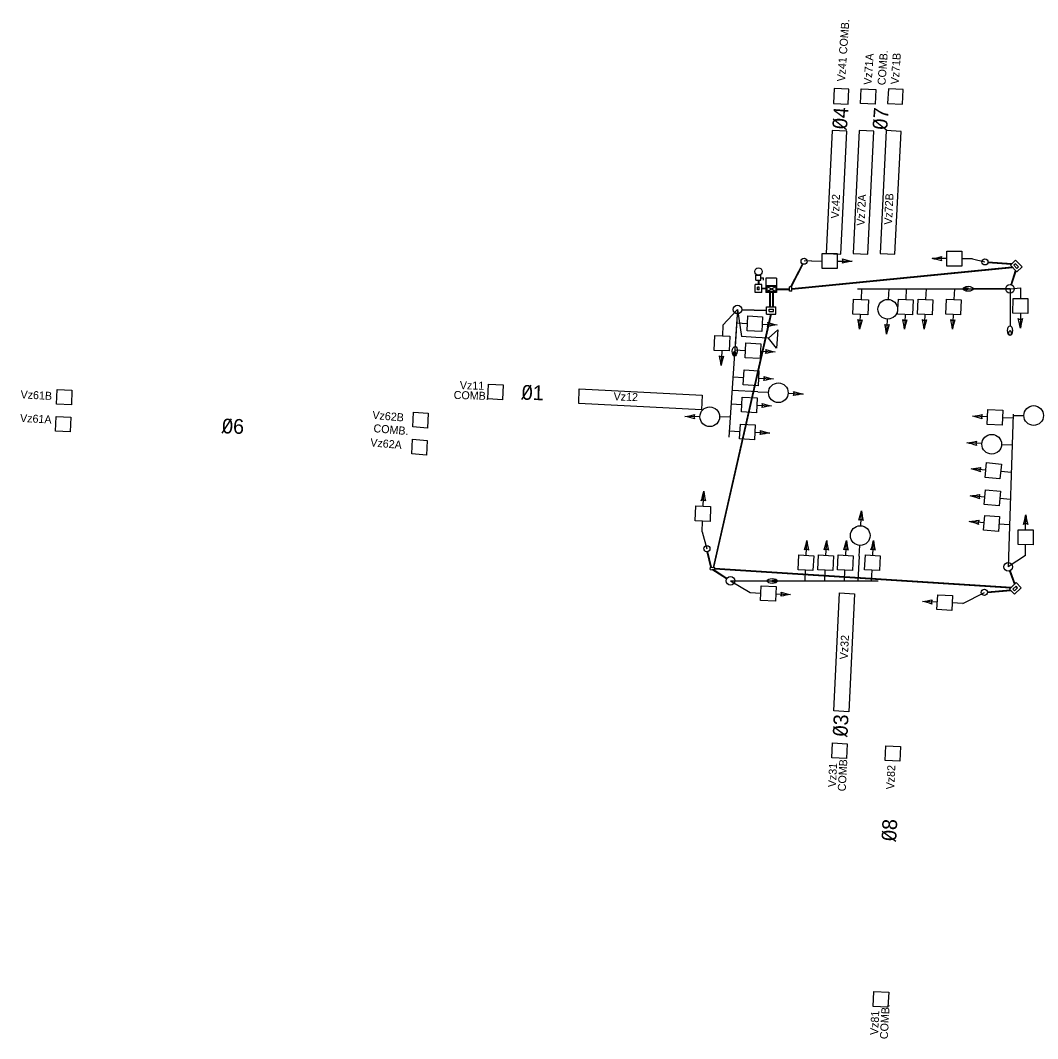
# Model space of a CAD drawing. Extents: x 647787 to 668496, y 640478 to 654412.
# Drawn here: x 647787.3 to 648200.7, y 648285.9 to 648699.5 of the extents above; entities that cross this region are included whole.
import ezdxf

# ---------------------------------------------------------------- set-up
doc = ezdxf.new("R2010")
doc.units = 0
for name, color, linetype in [('Default', 7, 'Continuous'), ('TEMP_SIGNAL_HEAD_STAGE 1A', 7, 'Continuous'), ('TEMP_SIGNAL_POLES_STAGE 1A', 7, 'Continuous'), ('TEMP_SIGNAL_POLES_STAGE 1B', 7, 'Continuous'), ('TEXT_TEMP_SIGNAL_POLES_STAGE 5', 7, 'Continuous')]:
    doc.layers.add(name, color=color, linetype=linetype)

msp = doc.modelspace()

# ---------------------------------------------------------------- linework, layer by layer
at = {"layer": 'Default'}
for p, q in [((648117.56, 648659.45), (648123, 648655.19)), ((648133.9, 648659.21), (648139.34, 648654.95)), ((647990.99, 648545.5), (647994.86, 648551.28)), ((647869.23, 648531.84), (647873.1, 648537.62)), ((648117.67, 648412.67), (648123.23, 648408.56)), ((648137.49, 648370.17), (648143.05, 648366.07))]:
    msp.add_line(p, q, dxfattribs=at)
at = {"layer": 'TEMP_SIGNAL_HEAD_STAGE 1A'}
for p, q in [((648105.08, 648600.6), (648100.19, 648591.24)), ((648105.3, 648600.49), (648100.47, 648591.23)), ((648100.79, 648590.53), (648190.24, 648599.38)), ((648100.79, 648590.28), (648190.47, 648599.15)), ((648189.91, 648600.32), (648180.42, 648601.03)), ((648190.14, 648600.55), (648180.47, 648601.28)), ((648191.68, 648602.07), (648189.61, 648600.02)), ((648192.25, 648597.36), (648189.61, 648600.02)), ((648191.67, 648600.66), (648191.02, 648600.01)), ((648192.25, 648598.77), (648191.02, 648600.01)), ((648192.9, 648599.42), (648191.67, 648600.66)), ((648194.32, 648599.41), (648191.68, 648602.07)), ((648192.9, 648599.42), (648192.25, 648598.77)), ((648194.32, 648599.41), (648192.25, 648597.36)), ((648086.19, 648595.95), (648088.19, 648595.95)), ((648086.19, 648593.95), (648086.19, 648595.95)), ((648088.19, 648593.95), (648088.19, 648595.95)), ((648088.19, 648594.95), (648089.19, 648594.95)), ((648089.19, 648593.95), (648089.19, 648594.95)), ((648189.84, 648592.17), (648191.68, 648597.93)), ((648190.08, 648592.1), (648191.88, 648597.73)), ((648085.82, 648588.99), (648085.82, 648592.18)), ((648088.55, 648592.18), (648085.82, 648592.18)), ((648086.19, 648593.95), (648088.19, 648593.95)), ((648086.82, 648589.99), (648086.82, 648591.18)), ((648087.55, 648591.18), (648086.82, 648591.18)), ((648087.06, 648593.95), (648087.06, 648592.18)), ((648087.31, 648593.95), (648087.31, 648592.18)), ((648087.55, 648589.99), (648087.55, 648591.18)), ((648088.55, 648588.99), (648088.55, 648592.18)), ((648099.87, 648589.49), (648099.88, 648591.24)), ((648100.79, 648591.23), (648099.88, 648591.24)), ((648100.78, 648589.48), (648100.79, 648591.23)), ((648088.55, 648588.99), (648085.82, 648588.99)), ((648087.55, 648589.99), (648086.82, 648589.99)), ((648090.26, 648590.59), (648088.55, 648590.66)), ((648090.26, 648590.34), (648088.55, 648590.41)), ((648091.66, 648588.99), (648091.66, 648583.14)), ((648091.91, 648588.99), (648091.91, 648583.14)), ((648092.91, 648588.99), (648092.91, 648583.14)), ((648093.16, 648588.99), (648093.16, 648583.14)), ((648094.59, 648590.49), (648099.87, 648590.49)), ((648094.59, 648590.24), (648099.87, 648590.24)), ((648100.78, 648589.48), (648099.87, 648589.49)), ((648090.54, 648583.14), (648094.29, 648583.14)), ((648090.54, 648580.22), (648090.54, 648583.14)), ((648094.29, 648580.22), (648094.29, 648583.14)), ((648092.06, 648580.22), (648068.75, 648477.3)), ((648092.31, 648580.22), (648069, 648477.28)), ((648080.47, 648581.86), (648090.54, 648581.58)), ((648080.48, 648582.11), (648090.54, 648581.83)), ((648090.54, 648580.22), (648094.29, 648580.22)), ((648091.54, 648581.22), (648091.54, 648582.14)), ((648091.54, 648582.14), (648093.29, 648582.14)), ((648091.54, 648581.22), (648093.29, 648581.22)), ((648093.29, 648581.22), (648093.29, 648582.14)), ((648067.91, 648477.34), (648066.4, 648483.62)), ((648068.18, 648477.33), (648066.64, 648483.68)), ((648067.62, 648476.44), (648067.67, 648477.35)), ((648067.62, 648476.44), (648069.37, 648476.35)), ((648067.67, 648477.35), (648069.42, 648477.26)), ((648074.25, 648472.62), (648068.24, 648476.4)), ((648074.39, 648472.83), (648068.75, 648476.38)), ((648069.37, 648476.35), (648069.42, 648477.26)), ((648069.39, 648476.67), (648189.81, 648469.04)), ((648069.4, 648476.92), (648190.05, 648469.28)), ((648189.21, 648475.82), (648191.19, 648470.41)), ((648189.45, 648475.91), (648191.38, 648470.6)), ((648189.23, 648468.46), (648191.89, 648471.1)), ((648193.94, 648469.03), (648191.89, 648471.1)), ((648180.25, 648467.38), (648189.54, 648468.14)), ((648180.27, 648467.13), (648189.77, 648467.91)), ((648191.28, 648466.39), (648189.23, 648468.46)), ((648190.64, 648468.46), (648191.88, 648469.69)), ((648191.29, 648467.81), (648190.64, 648468.46)), ((648191.28, 648466.39), (648193.94, 648469.03)), ((648191.29, 648467.81), (648192.53, 648469.04)), ((648192.53, 648469.04), (648191.88, 648469.69))]:
    msp.add_line(p, q, dxfattribs=at)
msp.add_circle((648087.19, 648597.45), 1.5, dxfattribs=at)
at = {"layer": 'TEMP_SIGNAL_POLES_STAGE 1A'}
for p, q in [((648108.8, 648601.77), (648105.76, 648601.65)), ((648108.8, 648601.77), (648113.15, 648601.75)), ((648119.21, 648601.73), (648125.25, 648601.7)), ((648163.79, 648602.71), (648157.75, 648602.74)), ((648174.2, 648602.67), (648169.85, 648602.69)), ((648174.2, 648602.67), (648179.22, 648601.38)), ((648189.43, 648590.47), (648193.72, 648590.9)), ((648193.72, 648590.9), (648193.7, 648586.55)), ((648127.43, 648590.47), (648189.43, 648590.47)), ((648129.1, 648590.47), (648128.89, 648586.13)), ((648140.16, 648590.47), (648139.95, 648586.15)), ((648147.29, 648590.47), (648147.08, 648586.13)), ((648155.3, 648590.47), (648155.09, 648586.13)), ((648166.81, 648590.47), (648166.61, 648586.13)), ((648189.43, 648590.47), (648174.43, 648590.47)), ((648189.43, 648590.47), (648189.43, 648575.47)), ((648072.7, 648575.74), (648078.73, 648582.03)), ((648078.73, 648582.03), (648075.18, 648530.15)), ((648078.73, 648582.03), (648077.7, 648567.06)), ((648078.73, 648582.03), (648080.25, 648571.03)), ((648128.6, 648580.07), (648128.31, 648574.04)), ((648146.79, 648580.07), (648146.51, 648574.04)), ((648154.8, 648580.07), (648154.51, 648574.04)), ((648166.32, 648580.07), (648166.03, 648574.04)), ((648193.67, 648580.49), (648193.65, 648574.45)), ((648072.7, 648575.74), (648072.53, 648571.4)), ((648078.36, 648576.62), (648082.7, 648576.4)), ((648088.75, 648576.09), (648094.79, 648575.79)), ((648139.57, 648578.15), (648139.28, 648572.1)), ((648086.12, 648570.68), (648080.25, 648571.03)), ((648072.29, 648565.34), (648072.05, 648559.31)), ((648077.61, 648565.64), (648081.95, 648565.42)), ((648088, 648565.12), (648094.04, 648564.81)), ((648076.85, 648554.67), (648081.2, 648554.45)), ((648087.25, 648554.14), (648093.28, 648553.83)), ((648086.97, 648548.65), (648076.48, 648549.18)), ((648086.97, 648548.65), (648091.3, 648548.43)), ((648099.29, 648548.02), (648105.34, 648547.71)), ((648076.1, 648543.69), (648080.44, 648543.47)), ((648086.5, 648543.16), (648092.53, 648542.86)), ((648063.41, 648538.5), (648057.34, 648538.56)), ((648075.74, 648538.37), (648071.41, 648538.42)), ((648180.28, 648538.4), (648174.24, 648538.71)), ((648190.67, 648537.87), (648186.33, 648538.09)), ((648190.72, 648539.48), (648188.73, 648477.51)), ((648190.71, 648538.94), (648195.04, 648538.96)), ((648075.35, 648532.72), (648079.69, 648532.49)), ((648085.75, 648532.19), (648091.78, 648531.88)), ((648178.01, 648527.56), (648171.95, 648527.9)), ((648190.32, 648526.88), (648186, 648527.12)), ((648179.6, 648516.82), (648173.58, 648517.37)), ((648189.97, 648515.88), (648185.64, 648516.27)), ((648064.74, 648502.18), (648064.98, 648508.21)), ((648179.25, 648505.83), (648173.23, 648506.37)), ((648189.61, 648504.88), (648185.28, 648505.28)), ((648128.75, 648494.23), (648129.05, 648500.29)), ((648064.33, 648491.78), (648064.5, 648496.12)), ((648178.91, 648495.41), (648172.89, 648495.93)), ((648195.78, 648492.58), (648195.8, 648498.62)), ((648064.33, 648491.78), (648066.23, 648484.86)), ((648189.28, 648494.52), (648184.95, 648494.89)), ((648106.63, 648482.19), (648106.93, 648488.22)), ((648114.64, 648482.19), (648114.94, 648488.22)), ((648122.65, 648482.19), (648122.95, 648488.22)), ((648133.66, 648482.19), (648133.96, 648488.22)), ((648128.14, 648481.92), (648128.36, 648486.24)), ((648195.74, 648482.17), (648195.75, 648486.52)), ((648128.14, 648481.92), (648127.65, 648471.79)), ((648195.74, 648482.17), (648188.73, 648477.51)), ((648106.12, 648471.79), (648106.33, 648476.13)), ((648114.13, 648471.79), (648114.34, 648476.13)), ((648122.14, 648471.79), (648122.35, 648476.13)), ((648133.15, 648471.79), (648133.37, 648476.13)), ((648075.8, 648471.79), (648135.8, 648471.79)), ((648075.8, 648471.79), (648083.85, 648467.06)), ((648075.8, 648471.79), (648090.8, 648471.79)), ((648083.85, 648467.07), (648088.2, 648466.85)), ((648170.29, 648462.64), (648179.02, 648467.16)), ((648094.25, 648466.54), (648100.28, 648466.23)), ((648159.89, 648463.17), (648153.86, 648463.48)), ((648170.29, 648462.64), (648165.95, 648462.86))]:
    msp.add_line(p, q, dxfattribs=at)
for points in [[(648113.14, 648598.72), (648113.16, 648604.78), (648119.23, 648604.76), (648119.2, 648598.69)], [(648169.86, 648605.72), (648169.84, 648599.65), (648163.78, 648599.68), (648163.8, 648605.74)], [(648125.86, 648586.27), (648131.92, 648585.98), (648131.63, 648579.93), (648125.57, 648580.22)], [(648144.05, 648586.27), (648150.11, 648585.98), (648149.82, 648579.93), (648143.76, 648580.22)], [(648152.06, 648586.27), (648158.12, 648585.98), (648157.83, 648579.93), (648151.77, 648580.22)], [(648163.58, 648586.27), (648169.63, 648585.98), (648169.34, 648579.93), (648163.29, 648580.22)], [(648190.67, 648586.57), (648196.73, 648586.54), (648196.71, 648580.48), (648190.64, 648580.5)], [(648082.55, 648573.37), (648082.85, 648579.43), (648088.91, 648579.12), (648088.6, 648573.06)], [(648069.5, 648571.52), (648075.56, 648571.28), (648075.32, 648565.22), (648069.26, 648565.46)], [(648081.79, 648562.39), (648082.1, 648568.45), (648088.16, 648568.14), (648087.85, 648562.09)], [(648081.04, 648551.42), (648081.35, 648557.48), (648087.4, 648557.17), (648087.1, 648551.11)], [(648080.29, 648540.44), (648080.6, 648546.5), (648086.65, 648546.19), (648086.35, 648540.14)], [(648186.49, 648541.12), (648186.18, 648535.06), (648180.12, 648535.37), (648180.43, 648541.43)], [(648079.54, 648529.47), (648079.85, 648535.52), (648085.9, 648535.22), (648085.59, 648529.16)], [(648185.91, 648519.29), (648185.36, 648513.25), (648179.32, 648513.8), (648179.87, 648519.84)], [(648185.56, 648508.3), (648185.01, 648502.26), (648178.97, 648502.81), (648179.52, 648508.85)], [(648067.53, 648496), (648061.47, 648496.24), (648061.71, 648502.3), (648067.77, 648502.06)], [(648185.21, 648497.91), (648184.69, 648491.87), (648178.65, 648492.39), (648179.17, 648498.43)], [(648198.79, 648486.51), (648192.72, 648486.53), (648192.75, 648492.6), (648198.81, 648492.57)], [(648109.36, 648475.98), (648103.3, 648476.28), (648103.6, 648482.34), (648109.66, 648482.04)], [(648117.37, 648475.98), (648111.31, 648476.28), (648111.61, 648482.34), (648117.67, 648482.04)], [(648125.38, 648475.98), (648119.32, 648476.28), (648119.62, 648482.34), (648125.68, 648482.04)], [(648136.39, 648475.98), (648130.34, 648476.28), (648130.64, 648482.34), (648136.69, 648482.04)], [(648088.04, 648463.82), (648088.35, 648469.87), (648094.4, 648469.57), (648094.1, 648463.51)], [(648166.1, 648465.89), (648165.8, 648459.83), (648159.74, 648460.14), (648160.05, 648466.2)]]:
    msp.add_lwpolyline(points, close=True, dxfattribs=at)
msp.add_lwpolyline([(648091.23, 648570.37), (648095.04, 648573.75), (648094.6, 648566.38), (648091.23, 648570.37), (648086.12, 648570.68)], dxfattribs=at)
for centre, radius in [((648105.76, 648601.65), 1.25), ((648179.22, 648601.38), 1.25), ((648189.43, 648590.47), 1.75), ((648078.73, 648582.03), 1.75), ((648139.76, 648582.15), 4), ((648095.29, 648548.22), 4), ((648067.41, 648538.46), 4), ((648199.04, 648538.99), 4), ((648182, 648527.34), 4), ((648128.55, 648490.24), 4), ((648066.23, 648484.86), 1.25), ((648188.73, 648477.51), 1.75), ((648075.8, 648471.79), 1.75), ((648179.02, 648467.16), 1.25)]:
    msp.add_circle(centre, radius, dxfattribs=at)
for centre, radius, start, end in [((648153.45, 648631.89), 29.47, 278.3758, 286.1139), ((648163.01, 648602.71), 1.63, 147.9202, 211.6148), ((648119.99, 648601.72), 1.63, 327.9202, 31.6148), ((648129.78, 648630.82), 29.47, 253.421, 261.1592), ((648129.55, 648572.54), 29.47, 98.3758, 106.1139), ((648153.22, 648573.61), 29.47, 73.421, 81.1592), ((648193.67, 648579.72), 1.63, 237.9208, 301.6154), ((648164.49, 648570.16), 29.47, 8.3764, 16.1145), ((648222.77, 648569.92), 29.47, 163.4217, 171.1598), ((648089.53, 648576.05), 1.63, 325.2481, 28.9427), ((648097.72, 648546.46), 29.47, 95.7037, 103.4418), ((648100.67, 648604.66), 29.47, 250.749, 258.4871), ((648128.56, 648579.3), 1.63, 235.4157, 299.1103), ((648098.99, 648571.02), 29.47, 5.8713, 13.6095), ((648157.21, 648568.24), 29.47, 160.9166, 168.6547), ((648139.53, 648577.36), 1.63, 235.4131, 299.1077), ((648109.96, 648569.08), 29.47, 5.8797, 13.6179), ((648168.17, 648566.3), 29.47, 160.9241, 168.6622), ((648146.76, 648579.3), 1.63, 235.4157, 299.1103), ((648117.19, 648571.02), 29.47, 5.8713, 13.6095), ((648175.4, 648568.24), 29.47, 160.9166, 168.6547), ((648154.77, 648579.3), 1.63, 235.4157, 299.1103), ((648125.2, 648571.02), 29.47, 5.8713, 13.6095), ((648183.41, 648568.24), 29.47, 160.9166, 168.6547), ((648166.28, 648579.3), 1.63, 235.4157, 299.1103), ((648136.71, 648571.02), 29.47, 5.8713, 13.6095), ((648194.92, 648568.24), 29.47, 160.9166, 168.6547), ((648072.26, 648564.57), 1.63, 235.8929, 299.5875), ((648042.76, 648556.05), 29.47, 6.3485, 14.0866), ((648100.99, 648553.75), 29.47, 161.3938, 169.1319), ((648088.78, 648565.08), 1.63, 325.2481, 28.9427), ((648096.96, 648535.48), 29.47, 95.7037, 103.4418), ((648099.92, 648593.69), 29.47, 250.749, 258.4871), ((648088.02, 648554.1), 1.63, 325.2481, 28.9427), ((648096.21, 648524.51), 29.47, 95.7037, 103.4418), ((648099.17, 648582.71), 29.47, 250.749, 258.4871), ((648100.08, 648547.98), 1.63, 325.2481, 28.9427), ((648108.28, 648518.39), 29.47, 95.7147, 103.4528), ((648111.22, 648576.59), 29.47, 250.7591, 258.4972), ((648087.27, 648543.12), 1.63, 325.2481, 28.9427), ((648095.46, 648513.53), 29.47, 95.7037, 103.4418), ((648098.41, 648571.74), 29.47, 250.749, 258.4871), ((648053.23, 648567.75), 29.47, 278.0238, 285.7619), ((648052.64, 648509.47), 29.47, 73.0681, 80.8063), ((648062.61, 648538.51), 1.63, 147.5572, 211.2518), ((648171.31, 648568.03), 29.47, 275.7037, 283.4418), ((648168.36, 648509.83), 29.47, 70.749, 78.4871), ((648179.5, 648538.44), 1.63, 145.2481, 208.9427), ((648086.52, 648532.15), 1.63, 325.2481, 28.9427), ((648097.66, 648560.76), 29.47, 250.749, 258.4871), ((648094.71, 648502.55), 29.47, 95.7037, 103.4418), ((648169.16, 648557.24), 29.47, 275.4377, 283.1759), ((648165.94, 648499.05), 29.47, 70.4821, 78.2202), ((648177.21, 648527.6), 1.63, 144.9711, 208.6657), ((648171.83, 648546.79), 29.47, 273.4111, 281.1492), ((648166.55, 648488.75), 29.47, 68.4564, 76.1945), ((648178.83, 648516.89), 1.63, 142.9555, 206.6501), ((648036.03, 648513.77), 29.47, 341.3938, 349.1319), ((648094.27, 648511.47), 29.47, 186.3485, 194.0866), ((648064.77, 648502.95), 1.63, 55.8929, 119.5875), ((648171.48, 648535.79), 29.47, 273.4111, 281.1492), ((648166.2, 648477.75), 29.47, 68.4564, 76.1945), ((648178.48, 648505.9), 1.63, 142.9555, 206.6501), ((648100.16, 648506.12), 29.47, 340.8488, 348.5869), ((648158.37, 648503.27), 29.47, 185.8045, 193.5426), ((648128.79, 648495.03), 1.63, 55.3378, 119.0325), ((648170.99, 648525.34), 29.47, 273.7041, 281.4422), ((648166, 648467.27), 29.47, 68.7494, 76.4875), ((648178.14, 648495.48), 1.63, 143.2485, 206.9431), ((648166.68, 648503.15), 29.47, 343.4217, 351.1598), ((648224.96, 648502.92), 29.47, 188.3764, 196.1145), ((648195.78, 648493.36), 1.63, 57.9208, 121.6154), ((648078.04, 648494.06), 29.47, 340.8387, 348.5768), ((648136.25, 648491.2), 29.47, 185.7935, 193.5316), ((648086.05, 648494.06), 29.47, 340.8387, 348.5768), ((648144.26, 648491.2), 29.47, 185.7935, 193.5316), ((648094.06, 648494.06), 29.47, 340.8387, 348.5768), ((648152.27, 648491.2), 29.47, 185.7935, 193.5316), ((648105.07, 648494.06), 29.47, 340.8387, 348.5768), ((648163.28, 648491.2), 29.47, 185.7935, 193.5316), ((648106.67, 648482.96), 1.63, 55.3378, 119.0325), ((648114.68, 648482.96), 1.63, 55.3378, 119.0325), ((648122.69, 648482.96), 1.63, 55.3378, 119.0325), ((648133.7, 648482.96), 1.63, 55.3378, 119.0325), ((648095.02, 648466.5), 1.63, 325.2443, 28.9389), ((648106.17, 648495.11), 29.47, 250.7451, 258.4833), ((648103.21, 648436.9), 29.47, 95.6999, 103.438), ((648150.93, 648492.8), 29.47, 275.6999, 283.438), ((648147.98, 648434.6), 29.47, 70.7451, 78.4833), ((648159.12, 648463.21), 1.63, 145.2443, 208.9389)]:
    msp.add_arc(centre, radius, start, end, dxfattribs=at)
for centre, major_axis in [((648172.43, 648590.47), (-2, 0)), ((648171.43, 648590.47), (1, 0)), ((648189.43, 648573.47), (0, -2)), ((648189.43, 648572.47), (0, 1)), ((648077.57, 648565.07), (-0.14, -2)), ((648077.5, 648564.07), (0.068, 0.998)), ((648092.8, 648471.79), (2, 0)), ((648093.8, 648471.79), (-1, 0))]:
    msp.add_ellipse(centre, major_axis=major_axis, ratio=0.5, dxfattribs=at)
at = {"layer": 'TEMP_SIGNAL_POLES_STAGE 1B'}
for p, q in [((648117.96, 648671.78), (648117.67, 648665.79)), ((648123.96, 648671.49), (648117.96, 648671.78)), ((648123.66, 648665.49), (648123.96, 648671.49)), ((648128.68, 648665.74), (648128.98, 648671.74)), ((648128.98, 648671.74), (648134.97, 648671.44)), ((648134.97, 648671.44), (648134.67, 648665.45)), ((648139.99, 648671.69), (648139.69, 648665.7)), ((648145.98, 648671.4), (648139.99, 648671.69)), ((648145.68, 648665.4), (648145.98, 648671.4)), ((648117.67, 648665.79), (648123.66, 648665.49)), ((648134.67, 648665.45), (648128.68, 648665.74)), ((648139.69, 648665.7), (648145.68, 648665.4)), ((648117.13, 648654.8), (648114.67, 648604.86)), ((648123.12, 648654.51), (648117.13, 648654.8)), ((648120.66, 648604.57), (648123.12, 648654.51)), ((648128.14, 648654.76), (648125.68, 648604.82)), ((648134.13, 648654.46), (648128.14, 648654.76)), ((648131.67, 648604.52), (648134.13, 648654.46)), ((648139.15, 648654.71), (648136.69, 648604.77)), ((648145.14, 648654.42), (648139.15, 648654.71)), ((648142.69, 648604.48), (648145.14, 648654.42)), ((648114.67, 648604.86), (648120.66, 648604.57)), ((648125.68, 648604.82), (648131.67, 648604.52)), ((648136.69, 648604.77), (648142.69, 648604.48)), ((647977.22, 648545.71), (647977.46, 648551.7)), ((647977.46, 648551.7), (647983.45, 648551.4)), ((647983.45, 648551.4), (647983.21, 648545.4)), ((648014.18, 648543.83), (648014.41, 648549.83)), ((648014.41, 648549.83), (648064.35, 648547.29)), ((647983.21, 648545.4), (647977.22, 648545.71)), ((648064.35, 648547.29), (648064.11, 648541.3)), ((648064.11, 648541.3), (648014.18, 648543.83)), ((647946.75, 648534.4), (647946.99, 648540.4)), ((647952.97, 648539.89), (647952.73, 648533.89)), ((647946.32, 648523.4), (647946.55, 648529.4)), ((647952.54, 648528.88), (647952.3, 648522.88)), ((648117.89, 648418.96), (648120.18, 648466.9)), ((648120.18, 648466.9), (648126.17, 648466.6)), ((648126.17, 648466.6), (648123.88, 648418.65)), ((648123.88, 648418.65), (648117.89, 648418.96)), ((648116.98, 648399.98), (648117.27, 648405.97)), ((648117.27, 648405.97), (648123.26, 648405.67)), ((648123.26, 648405.67), (648122.97, 648399.68)), ((648138.63, 648398.88), (648138.92, 648404.87)), ((648138.92, 648404.87), (648144.91, 648404.57)), ((648144.91, 648404.57), (648144.62, 648398.58)), ((648122.97, 648399.68), (648116.98, 648399.98)), ((648144.62, 648398.58), (648138.63, 648398.88)), ((648133.85, 648298.99), (648134.14, 648304.99)), ((648134.14, 648304.99), (648140.13, 648304.68)), ((648140.13, 648304.68), (648139.84, 648298.69)), ((648139.84, 648298.69), (648133.85, 648298.99))]:
    msp.add_line(p, q, dxfattribs=at)
for points in [[(647808, 648543.36), (647802, 648543.59), (647802.24, 648549.59), (647808.23, 648549.35)], [(647807.56, 648532.36), (647801.57, 648532.6), (647801.8, 648538.6), (647807.8, 648538.36)]]:
    msp.add_lwpolyline(points, close=True, dxfattribs=at)
for points in [[(647946.99, 648540.4), (647952.97, 648539.89)], [(647952.73, 648533.89), (647946.75, 648534.4)], [(647946.55, 648529.4), (647952.54, 648528.88)], [(647952.3, 648522.88), (647946.32, 648523.4)]]:
    msp.add_lwpolyline(points, dxfattribs=at)
at = {"layer": 'TEXT_TEMP_SIGNAL_POLES_STAGE 5'}
for p, q in [((648090.26, 648594.73), (648090.26, 648588.99)), ((648094.59, 648594.73), (648090.26, 648594.73)), ((648094.59, 648591.73), (648090.26, 648591.73)), ((648090.59, 648591.4), (648090.59, 648589.32)), ((648094.26, 648591.4), (648090.59, 648591.4)), ((648094.24, 648589.32), (648090.59, 648591.4)), ((648090.59, 648589.32), (648094.26, 648591.4)), ((648094.26, 648591.4), (648094.26, 648589.32)), ((648094.59, 648594.73), (648094.59, 648588.99)), ((648094.59, 648588.99), (648090.26, 648588.99)), ((648094.26, 648589.32), (648090.59, 648589.32))]:
    msp.add_line(p, q, dxfattribs=at)

# ---------------------------------------------------------------- texts
at = {"layer": 'Default'}
for s, rotation, p in [('04', 85.5313, (648123.14, 648655.14)), ('07', 85.5313, (648139.48, 648654.9)), ('01', 358.3326, (647990.93, 648545.42)), ('06', 358.3326, (647869.16, 648531.76)), ('03', 87.1376, (648123.37, 648408.52)), ('08', 87.1376, (648143.19, 648366.02))]:
    msp.add_text(s, height=6, rotation=rotation, dxfattribs=at).set_placement(p)
at = {"layer": 'TEMP_SIGNAL_POLES_STAGE 1B'}
for s, rotation, p in [('Vz41 COMB.', 85.9189, (648122.36, 648674.57)), ('Vz71A', 85.9189, (648133.14, 648673.19)), ('COMB.', 85.9189, (648138.79, 648673.07)), ('Vz71B', 85.9189, (648144.17, 648673.4)), ('Vz42', 87.1709, (648119.87, 648618.93)), ('Vz72A', 87.1709, (648130.3, 648615.99)), ('Vz72B', 87.1709, (648141.47, 648616.4)), ('Vz11', 358.2413, (647965.8, 648549.73)), ('Vz61B', 356.9063, (647787.26, 648545.98)), ('COMB.', 358.2413, (647963.32, 648545.74)), ('Vz12', 357.8394, (648028.29, 648545.2)), ('Vz61A', 356.9063, (647787.06, 648536.4)), ('Vz62B', 355.0374, (647930.2, 648537.65)), ('COMB.', 355.0374, (647930.66, 648532.26)), ('Vz62A', 355.0374, (647929.36, 648526.49)), ('Vz32', 86.9366, (648123.47, 648439.84)), ('Vz31', 86.9366, (648118.66, 648387.91)), ('COMB.', 86.9366, (648122.65, 648386.27)), ('Vz82', 86.9366, (648142.33, 648387.03)), ('COMB.', 86.9366, (648139.76, 648285.59)), ('Vz81', 86.9366, (648135.78, 648287.24))]:
    msp.add_text(s, height=3.25, rotation=rotation, dxfattribs=at).set_placement(p)

doc.saveas('drawing.dxf')
